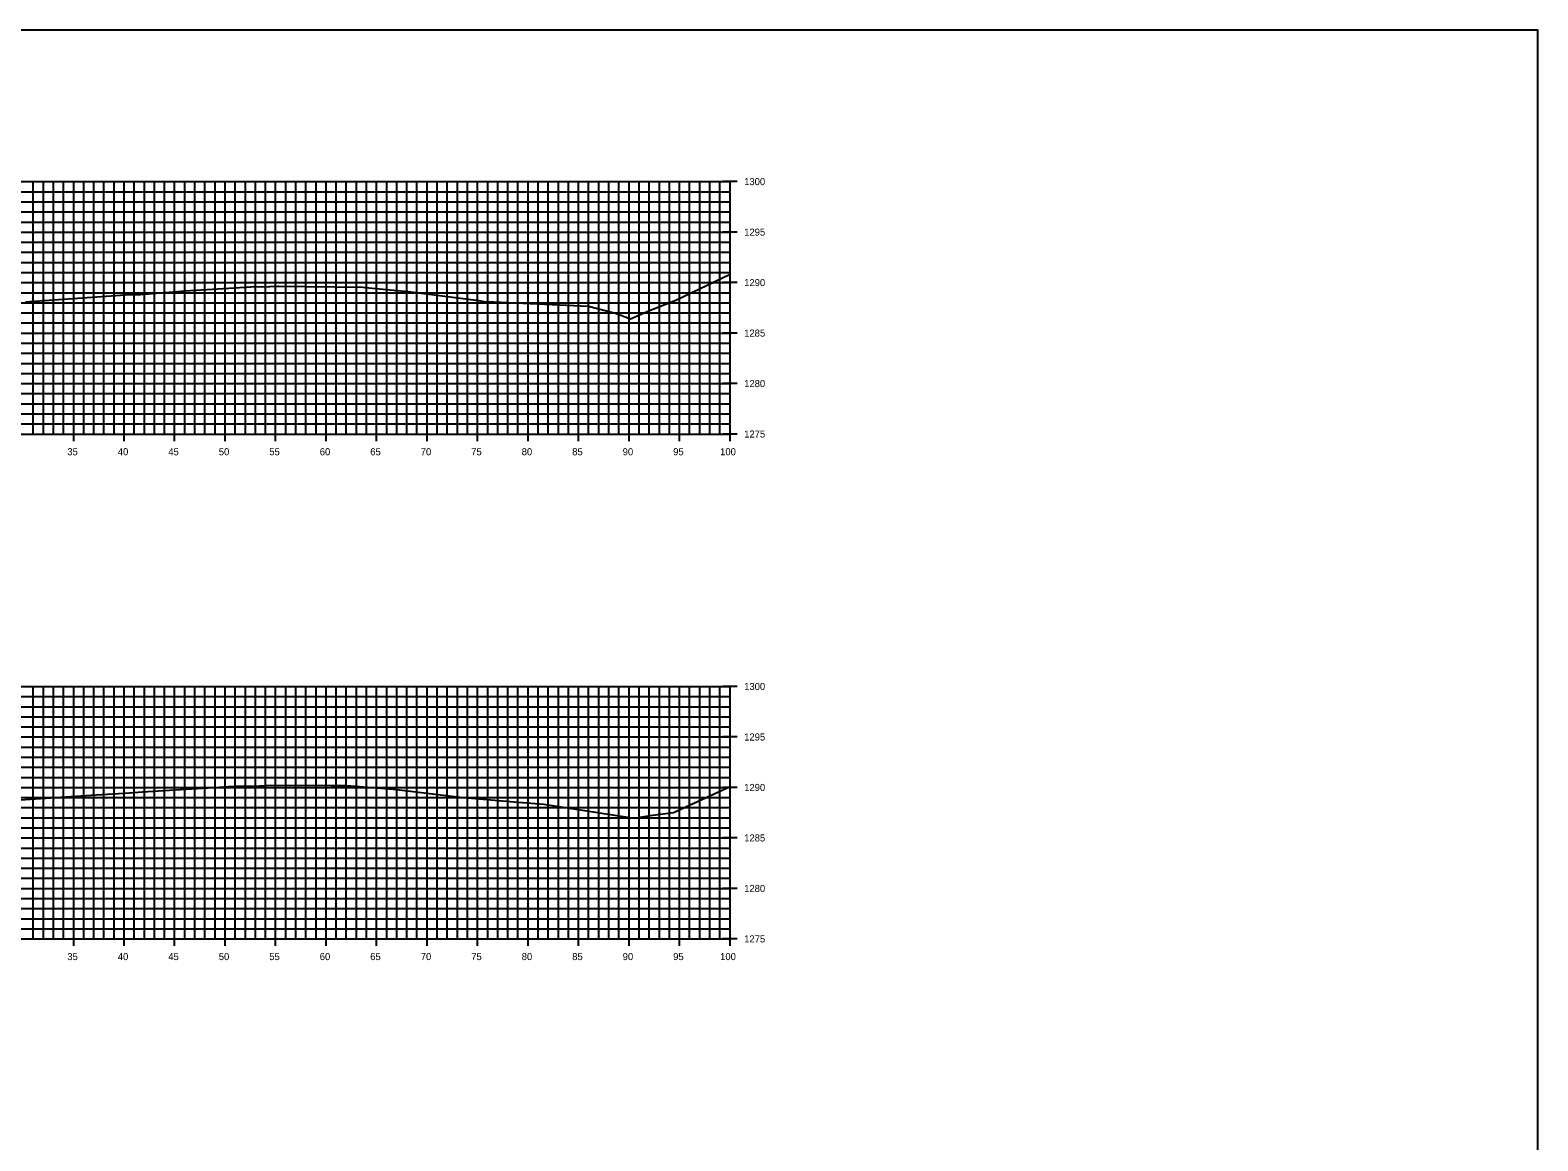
# Model space of a CAD drawing. Extents: x 674939 to 678919, y 750652 to 765176.
# Drawn here: x 678769.2 to 678918.5, y 755402.6 to 755512.6 of the extents above; entities that cross this region are included whole.
import ezdxf

# ---------------------------------------------------------------- set-up
doc = ezdxf.new("R2010")
doc.units = 0
for name, color, linetype in [('R_Axis', 7, 'Continuous'), ('R_Axis Annot', 7, 'Continuous'), ('R_Exist Surface', 7, 'Continuous'), ('R_Grid', 7, 'Continuous'), ('R_No Plot', 7, 'Continuous')]:
    doc.layers.add(name, color=color, linetype=linetype)

msp = doc.modelspace()

# ---------------------------------------------------------------- linework, layer by layer
at = {"layer": 'R_Axis'}
for p, q in [((678839.23, 755497.55), (678837.83, 755497.55)), ((678838.53, 755472.55), (678838.53, 755497.55)), ((678839.23, 755492.55), (678837.83, 755492.55)), ((678839.23, 755487.55), (678837.83, 755487.55)), ((678839.23, 755482.55), (678837.83, 755482.55)), ((678839.23, 755477.55), (678837.83, 755477.55)), ((678773.53, 755471.85), (678773.53, 755473.25)), ((678778.53, 755471.85), (678778.53, 755473.25)), ((678783.53, 755471.85), (678783.53, 755473.25)), ((678788.53, 755471.85), (678788.53, 755473.25)), ((678793.53, 755471.85), (678793.53, 755473.25)), ((678798.53, 755471.85), (678798.53, 755473.25)), ((678803.53, 755471.85), (678803.53, 755473.25)), ((678808.53, 755471.85), (678808.53, 755473.25)), ((678813.53, 755471.85), (678813.53, 755473.25)), ((678818.53, 755471.85), (678818.53, 755473.25)), ((678823.53, 755471.85), (678823.53, 755473.25)), ((678828.53, 755471.85), (678828.53, 755473.25)), ((678833.53, 755471.85), (678833.53, 755473.25)), ((678838.53, 755471.85), (678838.53, 755473.25)), ((678638.53, 755472.55), (678838.53, 755472.55)), ((678839.23, 755472.55), (678837.83, 755472.55)), ((678839.23, 755447.55), (678837.83, 755447.55)), ((678838.53, 755422.55), (678838.53, 755447.55)), ((678839.23, 755442.55), (678837.83, 755442.55)), ((678839.23, 755437.55), (678837.83, 755437.55)), ((678839.23, 755432.55), (678837.83, 755432.55)), ((678839.23, 755427.55), (678837.83, 755427.55)), ((678638.53, 755422.55), (678838.53, 755422.55)), ((678773.53, 755421.85), (678773.53, 755423.25)), ((678778.53, 755421.85), (678778.53, 755423.25)), ((678783.53, 755421.85), (678783.53, 755423.25)), ((678788.53, 755421.85), (678788.53, 755423.25)), ((678793.53, 755421.85), (678793.53, 755423.25)), ((678798.53, 755421.85), (678798.53, 755423.25)), ((678803.53, 755421.85), (678803.53, 755423.25)), ((678808.53, 755421.85), (678808.53, 755423.25)), ((678813.53, 755421.85), (678813.53, 755423.25)), ((678818.53, 755421.85), (678818.53, 755423.25)), ((678823.53, 755421.85), (678823.53, 755423.25)), ((678828.53, 755421.85), (678828.53, 755423.25)), ((678833.53, 755421.85), (678833.53, 755423.25)), ((678839.23, 755422.55), (678837.83, 755422.55)), ((678838.53, 755421.85), (678838.53, 755423.25))]:
    msp.add_line(p, q, dxfattribs=at)
at = {"layer": 'R_Exist Surface'}
for points in [[(678768.75, 755485.65), (678771.58, 755485.84), (678779.14, 755486.36), (678779.15, 755486.37), (678779.15, 755486.37), (678780.15, 755486.38), (678780.16, 755486.38), (678784.55, 755486.73), (678784.58, 755486.73), (678791.05, 755487.13), (678791.06, 755487.13), (678791.35, 755487.15), (678791.36, 755487.15), (678792.15, 755487.12), (678792.16, 755487.12), (678793.75, 755487.18), (678793.81, 755487.18), (678802.15, 755487.11), (678802.15, 755487.11), (678802.41, 755487.08), (678806.65, 755486.66), (678813.65, 755485.76), (678814.15, 755485.69), (678815.15, 755485.65), (678824.51, 755485.23), (678827.2, 755484.51), (678828.69, 755483.97), (678830.57, 755484.79), (678833.17, 755485.82), (678838.53, 755488.4)], [(678767.76, 755436.28), (678775.77, 755436.81), (678777.96, 755436.96), (678778.43, 755436.97), (678778.6, 755436.97), (678780.33, 755437.11), (678780.88, 755437.16), (678781.94, 755437.22), (678787.94, 755437.58), (678788.82, 755437.63), (678790.4, 755437.7), (678790.5, 755437.7), (678790.5, 755437.7), (678791.04, 755437.68), (678791.2, 755437.67), (678792.63, 755437.74), (678793, 755437.76), (678799.02, 755437.75), (678800.54, 755437.75), (678800.55, 755437.75), (678805.18, 755437.39), (678805.47, 755437.36), (678806.05, 755437.29), (678811.76, 755436.6), (678817.55, 755436.09), (678820.1, 755435.89), (678822.22, 755435.55), (678829.05, 755434.52), (678830.61, 755434.78), (678832.94, 755435.08), (678838.53, 755437.66)]]:
    msp.add_lwpolyline(points, dxfattribs=at)
at = {"layer": 'R_Grid'}
for p, q in [((678638.53, 755497.55), (678838.53, 755497.55)), ((678769.53, 755472.55), (678769.53, 755497.55)), ((678770.53, 755472.55), (678770.53, 755497.55)), ((678771.53, 755472.55), (678771.53, 755497.55)), ((678772.53, 755472.55), (678772.53, 755497.55)), ((678773.53, 755472.55), (678773.53, 755497.55)), ((678774.53, 755472.55), (678774.53, 755497.55)), ((678775.53, 755472.55), (678775.53, 755497.55)), ((678776.53, 755472.55), (678776.53, 755497.55)), ((678777.53, 755472.55), (678777.53, 755497.55)), ((678778.53, 755472.55), (678778.53, 755497.55)), ((678779.53, 755472.55), (678779.53, 755497.55)), ((678780.53, 755472.55), (678780.53, 755497.55)), ((678781.53, 755472.55), (678781.53, 755497.55)), ((678782.53, 755472.55), (678782.53, 755497.55)), ((678783.53, 755472.55), (678783.53, 755497.55)), ((678784.53, 755472.55), (678784.53, 755497.55)), ((678785.53, 755472.55), (678785.53, 755497.55)), ((678786.53, 755472.55), (678786.53, 755497.55)), ((678787.53, 755472.55), (678787.53, 755497.55)), ((678788.53, 755472.55), (678788.53, 755497.55)), ((678789.53, 755472.55), (678789.53, 755497.55)), ((678790.53, 755472.55), (678790.53, 755497.55)), ((678791.53, 755472.55), (678791.53, 755497.55)), ((678792.53, 755472.55), (678792.53, 755497.55)), ((678793.53, 755472.55), (678793.53, 755497.55)), ((678794.53, 755472.55), (678794.53, 755497.55)), ((678795.53, 755472.55), (678795.53, 755497.55)), ((678796.53, 755472.55), (678796.53, 755497.55)), ((678797.53, 755472.55), (678797.53, 755497.55)), ((678798.53, 755472.55), (678798.53, 755497.55)), ((678799.53, 755472.55), (678799.53, 755497.55)), ((678800.53, 755472.55), (678800.53, 755497.55)), ((678801.53, 755472.55), (678801.53, 755497.55)), ((678802.53, 755472.55), (678802.53, 755497.55)), ((678803.53, 755472.55), (678803.53, 755497.55)), ((678804.53, 755472.55), (678804.53, 755497.55)), ((678805.53, 755472.55), (678805.53, 755497.55)), ((678806.53, 755472.55), (678806.53, 755497.55)), ((678807.53, 755472.55), (678807.53, 755497.55)), ((678808.53, 755472.55), (678808.53, 755497.55)), ((678809.53, 755472.55), (678809.53, 755497.55)), ((678810.53, 755472.55), (678810.53, 755497.55)), ((678811.53, 755472.55), (678811.53, 755497.55)), ((678812.53, 755472.55), (678812.53, 755497.55)), ((678813.53, 755472.55), (678813.53, 755497.55)), ((678814.53, 755472.55), (678814.53, 755497.55)), ((678815.53, 755472.55), (678815.53, 755497.55)), ((678816.53, 755472.55), (678816.53, 755497.55)), ((678817.53, 755472.55), (678817.53, 755497.55)), ((678818.53, 755472.55), (678818.53, 755497.55)), ((678819.53, 755472.55), (678819.53, 755497.55)), ((678820.53, 755472.55), (678820.53, 755497.55)), ((678821.53, 755472.55), (678821.53, 755497.55)), ((678822.53, 755472.55), (678822.53, 755497.55)), ((678823.53, 755472.55), (678823.53, 755497.55)), ((678824.53, 755472.55), (678824.53, 755497.55)), ((678825.53, 755472.55), (678825.53, 755497.55)), ((678826.53, 755472.55), (678826.53, 755497.55)), ((678827.53, 755472.55), (678827.53, 755497.55)), ((678828.53, 755472.55), (678828.53, 755497.55)), ((678829.53, 755472.55), (678829.53, 755497.55)), ((678830.53, 755472.55), (678830.53, 755497.55)), ((678831.53, 755472.55), (678831.53, 755497.55)), ((678832.53, 755472.55), (678832.53, 755497.55)), ((678833.53, 755472.55), (678833.53, 755497.55)), ((678834.53, 755472.55), (678834.53, 755497.55)), ((678835.53, 755472.55), (678835.53, 755497.55)), ((678836.53, 755472.55), (678836.53, 755497.55)), ((678837.53, 755472.55), (678837.53, 755497.55)), ((678838.53, 755472.55), (678838.53, 755497.55)), ((678638.53, 755496.55), (678838.53, 755496.55)), ((678638.53, 755495.55), (678838.53, 755495.55)), ((678638.53, 755494.55), (678838.53, 755494.55)), ((678638.53, 755493.55), (678838.53, 755493.55)), ((678638.53, 755492.55), (678838.53, 755492.55)), ((678638.53, 755491.55), (678838.53, 755491.55)), ((678638.53, 755490.55), (678838.53, 755490.55)), ((678638.53, 755489.55), (678838.53, 755489.55)), ((678638.53, 755488.55), (678838.53, 755488.55)), ((678638.53, 755487.55), (678838.53, 755487.55)), ((678638.53, 755486.55), (678838.53, 755486.55)), ((678638.53, 755485.55), (678838.53, 755485.55)), ((678638.53, 755484.55), (678838.53, 755484.55)), ((678638.53, 755483.55), (678838.53, 755483.55)), ((678638.53, 755482.55), (678838.53, 755482.55)), ((678638.53, 755481.55), (678838.53, 755481.55)), ((678638.53, 755480.55), (678838.53, 755480.55)), ((678638.53, 755479.55), (678838.53, 755479.55)), ((678638.53, 755478.55), (678838.53, 755478.55)), ((678638.53, 755477.55), (678838.53, 755477.55)), ((678638.53, 755476.55), (678838.53, 755476.55)), ((678638.53, 755475.55), (678838.53, 755475.55)), ((678638.53, 755474.55), (678838.53, 755474.55)), ((678638.53, 755473.55), (678838.53, 755473.55)), ((678638.53, 755472.55), (678838.53, 755472.55)), ((678638.53, 755447.55), (678838.53, 755447.55)), ((678638.53, 755446.55), (678838.53, 755446.55)), ((678769.53, 755422.55), (678769.53, 755447.55)), ((678770.53, 755422.55), (678770.53, 755447.55)), ((678771.53, 755422.55), (678771.53, 755447.55)), ((678772.53, 755422.55), (678772.53, 755447.55)), ((678773.53, 755422.55), (678773.53, 755447.55)), ((678774.53, 755422.55), (678774.53, 755447.55)), ((678775.53, 755422.55), (678775.53, 755447.55)), ((678776.53, 755422.55), (678776.53, 755447.55)), ((678777.53, 755422.55), (678777.53, 755447.55)), ((678778.53, 755422.55), (678778.53, 755447.55)), ((678779.53, 755422.55), (678779.53, 755447.55)), ((678780.53, 755422.55), (678780.53, 755447.55)), ((678781.53, 755422.55), (678781.53, 755447.55)), ((678782.53, 755422.55), (678782.53, 755447.55)), ((678783.53, 755422.55), (678783.53, 755447.55)), ((678784.53, 755422.55), (678784.53, 755447.55)), ((678785.53, 755422.55), (678785.53, 755447.55)), ((678786.53, 755422.55), (678786.53, 755447.55)), ((678787.53, 755422.55), (678787.53, 755447.55)), ((678788.53, 755422.55), (678788.53, 755447.55)), ((678789.53, 755422.55), (678789.53, 755447.55)), ((678790.53, 755422.55), (678790.53, 755447.55)), ((678791.53, 755422.55), (678791.53, 755447.55)), ((678792.53, 755422.55), (678792.53, 755447.55)), ((678793.53, 755422.55), (678793.53, 755447.55)), ((678794.53, 755422.55), (678794.53, 755447.55)), ((678795.53, 755422.55), (678795.53, 755447.55)), ((678796.53, 755422.55), (678796.53, 755447.55)), ((678797.53, 755422.55), (678797.53, 755447.55)), ((678798.53, 755422.55), (678798.53, 755447.55)), ((678799.53, 755422.55), (678799.53, 755447.55)), ((678800.53, 755422.55), (678800.53, 755447.55)), ((678801.53, 755422.55), (678801.53, 755447.55)), ((678802.53, 755422.55), (678802.53, 755447.55)), ((678803.53, 755422.55), (678803.53, 755447.55)), ((678804.53, 755422.55), (678804.53, 755447.55)), ((678805.53, 755422.55), (678805.53, 755447.55)), ((678806.53, 755422.55), (678806.53, 755447.55)), ((678807.53, 755422.55), (678807.53, 755447.55)), ((678808.53, 755422.55), (678808.53, 755447.55)), ((678809.53, 755422.55), (678809.53, 755447.55)), ((678810.53, 755422.55), (678810.53, 755447.55)), ((678811.53, 755422.55), (678811.53, 755447.55)), ((678812.53, 755422.55), (678812.53, 755447.55)), ((678813.53, 755422.55), (678813.53, 755447.55)), ((678814.53, 755422.55), (678814.53, 755447.55)), ((678815.53, 755422.55), (678815.53, 755447.55)), ((678816.53, 755422.55), (678816.53, 755447.55)), ((678817.53, 755422.55), (678817.53, 755447.55)), ((678818.53, 755422.55), (678818.53, 755447.55)), ((678819.53, 755422.55), (678819.53, 755447.55)), ((678820.53, 755422.55), (678820.53, 755447.55)), ((678821.53, 755422.55), (678821.53, 755447.55)), ((678822.53, 755422.55), (678822.53, 755447.55)), ((678823.53, 755422.55), (678823.53, 755447.55)), ((678824.53, 755422.55), (678824.53, 755447.55)), ((678825.53, 755422.55), (678825.53, 755447.55)), ((678826.53, 755422.55), (678826.53, 755447.55)), ((678827.53, 755422.55), (678827.53, 755447.55)), ((678828.53, 755422.55), (678828.53, 755447.55)), ((678829.53, 755422.55), (678829.53, 755447.55)), ((678830.53, 755422.55), (678830.53, 755447.55)), ((678831.53, 755422.55), (678831.53, 755447.55)), ((678832.53, 755422.55), (678832.53, 755447.55)), ((678833.53, 755422.55), (678833.53, 755447.55)), ((678834.53, 755422.55), (678834.53, 755447.55)), ((678835.53, 755422.55), (678835.53, 755447.55)), ((678836.53, 755422.55), (678836.53, 755447.55)), ((678837.53, 755422.55), (678837.53, 755447.55)), ((678838.53, 755422.55), (678838.53, 755447.55)), ((678638.53, 755445.55), (678838.53, 755445.55)), ((678638.53, 755444.55), (678838.53, 755444.55)), ((678638.53, 755443.55), (678838.53, 755443.55)), ((678638.53, 755442.55), (678838.53, 755442.55)), ((678638.53, 755441.55), (678838.53, 755441.55)), ((678638.53, 755440.55), (678838.53, 755440.55)), ((678638.53, 755439.55), (678838.53, 755439.55)), ((678638.53, 755438.55), (678838.53, 755438.55)), ((678638.53, 755437.55), (678838.53, 755437.55)), ((678638.53, 755436.55), (678838.53, 755436.55)), ((678638.53, 755435.55), (678838.53, 755435.55)), ((678638.53, 755434.55), (678838.53, 755434.55)), ((678638.53, 755433.55), (678838.53, 755433.55)), ((678638.53, 755432.55), (678838.53, 755432.55)), ((678638.53, 755431.55), (678838.53, 755431.55)), ((678638.53, 755430.55), (678838.53, 755430.55)), ((678638.53, 755429.55), (678838.53, 755429.55)), ((678638.53, 755428.55), (678838.53, 755428.55)), ((678638.53, 755427.55), (678838.53, 755427.55)), ((678638.53, 755426.55), (678838.53, 755426.55)), ((678638.53, 755425.55), (678838.53, 755425.55)), ((678638.53, 755424.55), (678838.53, 755424.55)), ((678638.53, 755423.55), (678838.53, 755423.55)), ((678638.53, 755422.55), (678838.53, 755422.55))]:
    msp.add_line(p, q, dxfattribs=at)
at = {"layer": 'R_No Plot'}
msp.add_lwpolyline([(678578.53, 755292.55), (678918.53, 755292.55), (678918.53, 755512.55), (678578.53, 755512.55)], close=True, dxfattribs=at)

# ---------------------------------------------------------------- texts
at = {"layer": 'R_Axis Annot'}
for s, p in [('1300', (678839.93, 755497.2)), ('1295', (678839.93, 755492.2)), ('1290', (678839.93, 755487.2)), ('1285', (678839.93, 755482.2)), ('1280', (678839.93, 755477.2)), ('1275', (678839.93, 755472.2)), ('35', (678772.9, 755470.45)), ('40', (678777.9, 755470.45)), ('45', (678782.9, 755470.45)), ('50', (678787.9, 755470.45)), ('55', (678792.9, 755470.45)), ('60', (678797.9, 755470.45)), ('65', (678802.9, 755470.45)), ('70', (678807.9, 755470.45)), ('75', (678812.9, 755470.45)), ('80', (678817.9, 755470.45)), ('85', (678822.9, 755470.45)), ('90', (678827.9, 755470.45)), ('95', (678832.9, 755470.45)), ('100', (678837.55, 755470.45)), ('1300', (678839.93, 755447.2)), ('1295', (678839.93, 755442.2)), ('1290', (678839.93, 755437.2)), ('1285', (678839.93, 755432.2)), ('1280', (678839.93, 755427.2)), ('1275', (678839.93, 755422.2)), ('35', (678772.9, 755420.45)), ('40', (678777.9, 755420.45)), ('45', (678782.9, 755420.45)), ('50', (678787.9, 755420.45)), ('55', (678792.9, 755420.45)), ('60', (678797.9, 755420.45)), ('65', (678802.9, 755420.45)), ('70', (678807.9, 755420.45)), ('75', (678812.9, 755420.45)), ('80', (678817.9, 755420.45)), ('85', (678822.9, 755420.45)), ('90', (678827.9, 755420.45)), ('95', (678832.9, 755420.45)), ('100', (678837.55, 755420.45))]:
    msp.add_text(s, height=0.7, dxfattribs=at).set_placement(p)

doc.saveas('drawing.dxf')
